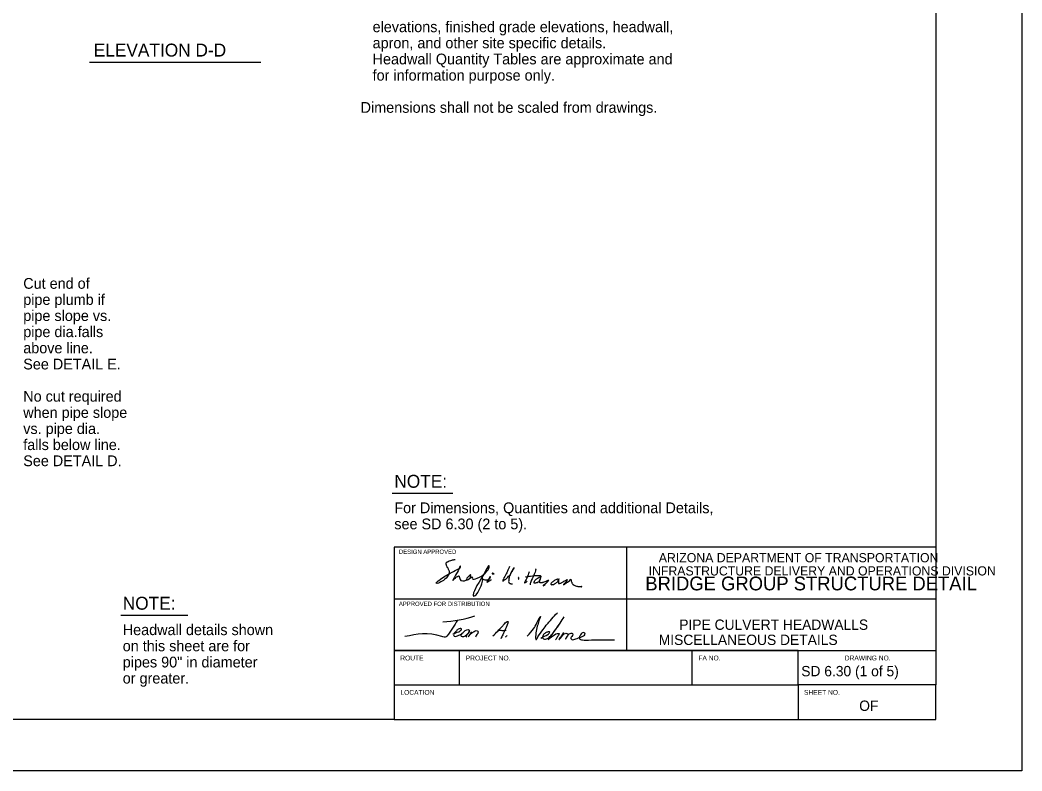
# Model space of a CAD drawing. Extents: x -0.08 to 2.83, y -0.03 to 1.92.
# Drawn here: x 1.621 to 2.833, y 0 to 0.909 of the extents above; entities that cross this region are included whole.
import ezdxf

# ---------------------------------------------------------------- set-up
doc = ezdxf.new("R2010")
doc.units = 0
for name, color, linetype in [('55', 7, 'Continuous'), ('57', 7, 'Continuous'), ('62', 7, 'Continuous'), ('63', 7, 'Continuous')]:
    doc.layers.add(name, color=color, linetype=linetype)

msp = doc.modelspace()

# ---------------------------------------------------------------- linework, layer by layer
at = {"layer": '57'}
for p, q in [((1.7051, 0.8577), (1.9125, 0.8577)), ((2.0713, 0.3361), (2.1448, 0.3361)), ((1.7428, 0.1885), (1.8239, 0.1885))]:
    msp.add_line(p, q, dxfattribs=at)
for points in [[(2.1477, 0.2556), (2.1468, 0.2557), (2.1458, 0.2554), (2.1449, 0.2553), (2.144, 0.255), (2.1431, 0.2548), (2.142, 0.2543), (2.1404, 0.2539), (2.139, 0.2533), (2.1381, 0.2528), (2.1376, 0.2526), (2.1371, 0.2524), (2.1366, 0.2519), (2.1364, 0.2514), (2.1363, 0.2504), (2.1365, 0.2499), (2.1367, 0.2491), (2.1371, 0.2482), (2.1375, 0.2473), (2.138, 0.2463), (2.1385, 0.2457), (2.1391, 0.2444), (2.1395, 0.2436), (2.1399, 0.2429), (2.1401, 0.2414), (2.1402, 0.2405), (2.1401, 0.2395), (2.1397, 0.238), (2.1389, 0.2363), (2.1382, 0.2352), (2.1366, 0.2333), (2.1351, 0.2323), (2.1333, 0.2307), (2.1317, 0.2297), (2.1303, 0.2288), (2.1288, 0.228), (2.1273, 0.2273), (2.1258, 0.2268), (2.125, 0.2269), (2.1246, 0.2276), (2.1248, 0.228), (2.1254, 0.2285), (2.1258, 0.2291), (2.1269, 0.23), (2.129, 0.2315), (2.1299, 0.2322), (2.1315, 0.2334), (2.1333, 0.2345), (2.1352, 0.2357), (2.1368, 0.2366), (2.1413, 0.2395), (2.1456, 0.2416), (2.1476, 0.2427), (2.1498, 0.2437), (2.1514, 0.2445), (2.1527, 0.2452), (2.1536, 0.2459), (2.154, 0.2465), (2.154, 0.2477), (2.1536, 0.2479), (2.1534, 0.2477), (2.1533, 0.2474), (2.1519, 0.2441), (2.151, 0.2423), (2.1479, 0.2371), (2.1462, 0.2339), (2.1454, 0.2326), (2.1446, 0.2309), (2.1447, 0.2307), (2.1462, 0.2324), (2.1479, 0.2338), (2.1493, 0.2349), (2.1504, 0.2355), (2.1503, 0.2355), (2.1517, 0.236), (2.1523, 0.2358), (2.1525, 0.2355), (2.1529, 0.2341), (2.153, 0.2328), (2.1535, 0.2316), (2.1542, 0.2306), (2.1566, 0.2301), (2.159, 0.2301), (2.1606, 0.2308), (2.1633, 0.2318), (2.1649, 0.233), (2.1659, 0.2341), (2.1662, 0.2362), (2.1665, 0.2374), (2.1662, 0.2377), (2.1657, 0.2374), (2.1644, 0.2361), (2.163, 0.2346), (2.1624, 0.234), (2.1617, 0.2332), (2.1613, 0.2319), (2.1615, 0.2311), (2.1631, 0.2319), (2.165, 0.2331), (2.1666, 0.2342), (2.1675, 0.2349)], [(2.1675, 0.2349), (2.1677, 0.235), (2.168, 0.235), (2.1683, 0.2343), (2.1681, 0.2332), (2.1685, 0.2325), (2.1694, 0.2323), (2.1707, 0.2323), (2.1722, 0.2326), (2.1743, 0.2334), (2.1771, 0.2347), (2.1792, 0.2359), (2.1811, 0.237), (2.184, 0.2394), (2.1867, 0.2425), (2.1874, 0.2434), (2.188, 0.2441), (2.1888, 0.2468), (2.1886, 0.2482), (2.188, 0.2484), (2.1852, 0.2437), (2.1836, 0.2401), (2.1786, 0.2322), (2.1764, 0.2285), (2.1737, 0.2244), (2.1708, 0.2182), (2.1698, 0.2158), (2.1692, 0.2126), (2.1693, 0.2119), (2.1701, 0.2114), (2.1719, 0.2123), (2.173, 0.2133), (2.1749, 0.2161), (2.1775, 0.2209), (2.1789, 0.2242), (2.1797, 0.2265), (2.1806, 0.2298), (2.1808, 0.2318), (2.1807, 0.2332), (2.1801, 0.2336), (2.1797, 0.2338), (2.18, 0.2331), (2.1807, 0.2327), (2.1813, 0.2322), (2.1824, 0.2317), (2.1835, 0.2313), (2.1841, 0.2313), (2.1858, 0.2312), (2.1865, 0.2313), (2.1879, 0.2317), (2.1891, 0.2327), (2.1894, 0.233), (2.1901, 0.2346), (2.1902, 0.2351), (2.1898, 0.2354), (2.1884, 0.2324), (2.1867, 0.2305), (2.1863, 0.2297), (2.186, 0.229), (2.1862, 0.2285), (2.1886, 0.23), (2.1895, 0.2305), (2.1906, 0.2312), (2.1914, 0.2318)], [(2.2132, 0.2473), (2.2128, 0.2463), (2.2119, 0.2446), (2.2111, 0.2429), (2.2099, 0.24), (2.2092, 0.2388), (2.2084, 0.2371), (2.2075, 0.2353), (2.2066, 0.2336), (2.2059, 0.2321), (2.2052, 0.2309), (2.205, 0.2303), (2.205, 0.23), (2.2051, 0.2299), (2.2054, 0.2298), (2.2057, 0.23), (2.2065, 0.2305), (2.2074, 0.2312), (2.2088, 0.2323), (2.2101, 0.2334), (2.2113, 0.2347), (2.2122, 0.2357), (2.2133, 0.2367), (2.214, 0.2375), (2.2148, 0.239), (2.216, 0.2409), (2.2167, 0.242), (2.2178, 0.2441), (2.2184, 0.2448), (2.2189, 0.2456), (2.2189, 0.2458), (2.2188, 0.2459), (2.2187, 0.246), (2.2185, 0.2459), (2.2181, 0.2452), (2.2172, 0.2441), (2.216, 0.242), (2.2157, 0.2413), (2.2153, 0.2404), (2.2149, 0.2396), (2.2139, 0.2375), (2.2133, 0.236), (2.213, 0.2348), (2.2127, 0.2337), (2.2125, 0.2324), (2.2123, 0.2307), (2.2122, 0.2295), (2.2123, 0.2283), (2.2126, 0.2278), (2.2132, 0.2273), (2.2138, 0.2269), (2.2143, 0.2267), (2.215, 0.2265), (2.2156, 0.2264), (2.2162, 0.2264), (2.2167, 0.2264)], [(2.2447, 0.2448), (2.245, 0.2443), (2.245, 0.2437), (2.2449, 0.2432), (2.2447, 0.2423), (2.2443, 0.2408), (2.2439, 0.2397), (2.2432, 0.238), (2.2427, 0.237), (2.2421, 0.2359), (2.241, 0.2334), (2.2406, 0.2326), (2.2395, 0.2304), (2.2393, 0.23), (2.239, 0.2291), (2.2386, 0.2277), (2.2384, 0.2267), (2.2382, 0.2256), (2.2381, 0.2252)], [(2.1947, 0.2388), (2.1943, 0.2388), (2.1938, 0.2389), (2.1934, 0.2391), (2.1931, 0.2393), (2.1928, 0.2393), (2.1925, 0.2393), (2.1924, 0.2392), (2.1922, 0.239), (2.1922, 0.2389), (2.1922, 0.2386), (2.1925, 0.2385), (2.1927, 0.2385), (2.193, 0.2385), (2.1935, 0.2386), (2.1938, 0.2386), (2.1942, 0.2386), (2.1946, 0.2387), (2.1947, 0.2387)], [(2.2244, 0.2324), (2.2247, 0.2331), (2.2246, 0.2338), (2.2244, 0.2341), (2.2241, 0.2341), (2.224, 0.2339), (2.2239, 0.2332), (2.224, 0.2326), (2.2242, 0.2323), (2.2243, 0.2322), (2.2244, 0.2322), (2.2244, 0.2324)], [(2.2371, 0.2412), (2.2367, 0.24), (2.2364, 0.239), (2.2358, 0.2372), (2.235, 0.2353), (2.2346, 0.2345), (2.2341, 0.2333), (2.2333, 0.2317), (2.2327, 0.2306), (2.2322, 0.2297), (2.2317, 0.2288), (2.2315, 0.2282), (2.2315, 0.2278), (2.2316, 0.2276), (2.2318, 0.2276), (2.232, 0.2276), (2.2326, 0.228), (2.2331, 0.2284), (2.2334, 0.2286), (2.2336, 0.2288), (2.2338, 0.2289), (2.234, 0.2291), (2.2342, 0.2293), (2.2344, 0.2295), (2.2345, 0.2296), (2.2347, 0.2298)], [(2.2325, 0.2346), (2.2332, 0.2348), (2.2342, 0.235), (2.2357, 0.2354), (2.2374, 0.2358), (2.2388, 0.2359), (2.2409, 0.2362), (2.243, 0.2364), (2.2448, 0.2366), (2.2463, 0.2366), (2.2475, 0.2366), (2.2482, 0.2366), (2.2495, 0.2365), (2.2505, 0.2364), (2.2509, 0.2362), (2.2511, 0.2357), (2.2507, 0.2337), (2.2506, 0.2334), (2.2501, 0.2318), (2.2497, 0.2308), (2.2492, 0.2298), (2.249, 0.2294), (2.2488, 0.2291), (2.2486, 0.2288), (2.2479, 0.2285), (2.2467, 0.2278), (2.2457, 0.2276), (2.2449, 0.2273), (2.2445, 0.2272), (2.244, 0.2272), (2.2435, 0.2274), (2.2433, 0.2275), (2.2433, 0.2277), (2.2433, 0.2281), (2.2433, 0.2288), (2.2435, 0.2293), (2.2437, 0.2298), (2.2441, 0.2306), (2.2447, 0.2312), (2.2456, 0.2321), (2.2463, 0.2326), (2.2468, 0.233), (2.2474, 0.2335), (2.2481, 0.2339), (2.249, 0.2344), (2.2496, 0.2347), (2.2503, 0.235), (2.2505, 0.235), (2.2508, 0.2349), (2.2508, 0.2347), (2.2506, 0.2334), (2.2505, 0.2332), (2.2503, 0.2322), (2.2499, 0.231), (2.2495, 0.23), (2.2494, 0.2295), (2.2494, 0.2293), (2.2493, 0.2291), (2.2493, 0.2287), (2.2494, 0.2284), (2.2498, 0.2281), (2.2499, 0.228), (2.2501, 0.228), (2.2505, 0.228), (2.2511, 0.228), (2.2515, 0.228), (2.2519, 0.2281), (2.2525, 0.2282), (2.2531, 0.2283), (2.2537, 0.2284), (2.2544, 0.2285), (2.2551, 0.2288), (2.2563, 0.2293), (2.2578, 0.2299), (2.2589, 0.2304), (2.2597, 0.2307), (2.2602, 0.231), (2.2608, 0.2311), (2.2609, 0.231), (2.2606, 0.2304), (2.26, 0.2298), (2.2593, 0.229), (2.2589, 0.2286), (2.2583, 0.228), (2.2572, 0.227), (2.2541, 0.2242), (2.2538, 0.224), (2.2541, 0.2241), (2.255, 0.2245), (2.2558, 0.2249), (2.2563, 0.2251), (2.2566, 0.2253)], [(2.2723, 0.2303), (2.2721, 0.2318), (2.2715, 0.2323), (2.271, 0.2321), (2.2692, 0.2314), (2.2681, 0.2308), (2.2672, 0.2302), (2.2664, 0.2297), (2.2655, 0.229), (2.2647, 0.2284), (2.2642, 0.2278), (2.2637, 0.2272), (2.2634, 0.2266), (2.2634, 0.2263), (2.2634, 0.2259), (2.2637, 0.2256), (2.264, 0.2255), (2.2644, 0.2254), (2.2646, 0.2254), (2.2652, 0.2255), (2.2655, 0.2256), (2.2664, 0.2258), (2.2678, 0.2263), (2.2686, 0.2269), (2.2695, 0.2275), (2.2703, 0.2281), (2.2711, 0.2287), (2.2718, 0.2294), (2.2724, 0.2301), (2.2731, 0.2315), (2.2732, 0.2322), (2.273, 0.2327), (2.2727, 0.2323), (2.2726, 0.2317), (2.2726, 0.231), (2.2726, 0.2299), (2.2726, 0.2291), (2.2726, 0.2283), (2.2726, 0.2277), (2.2726, 0.2269), (2.2727, 0.2267), (2.2728, 0.2267), (2.2737, 0.227), (2.2747, 0.2272), (2.2754, 0.2275), (2.2761, 0.2279), (2.2764, 0.228), (2.2772, 0.2284), (2.278, 0.2288), (2.2792, 0.2296), (2.2804, 0.2302), (2.2817, 0.2309), (2.2821, 0.2312), (2.283, 0.2318), (2.2831, 0.2317), (2.2829, 0.231), (2.2826, 0.2303), (2.2822, 0.2296), (2.2816, 0.2287), (2.2811, 0.2281), (2.2799, 0.2268), (2.2786, 0.2256), (2.2785, 0.2253), (2.2787, 0.2253), (2.2801, 0.2263), (2.2819, 0.2276), (2.2834, 0.2286), (2.2845, 0.2294), (2.2857, 0.2303), (2.287, 0.2318), (2.2871, 0.2318), (2.2873, 0.2321), (2.2874, 0.232), (2.2877, 0.2307), (2.2879, 0.2299), (2.2882, 0.229), (2.2885, 0.2284), (2.2888, 0.2277), (2.2891, 0.2271), (2.2896, 0.2263), (2.29, 0.2258), (2.2905, 0.2255), (2.2909, 0.2251), (2.2913, 0.2249), (2.2923, 0.2244), (2.2932, 0.2241), (2.2944, 0.2237), (2.2951, 0.2236), (2.2961, 0.2234), (2.297, 0.2233), (2.298, 0.2232), (2.2988, 0.2232), (2.2995, 0.2231), (2.3005, 0.223), (2.3009, 0.2229), (2.3007, 0.2231), (2.3004, 0.2233), (2.3001, 0.2235), (2.2999, 0.2236)]]:
    msp.add_lwpolyline(points, dxfattribs=at)
msp.add_arc((2.1258, 0.3265), 0.1461, 272.671, 288.185, dxfattribs=at)
msp.add_ellipse((2.1597, 0.1667), major_axis=(0.00445, 0.00414), ratio=0.425517, dxfattribs=at)
for points in [[(2.1503, 0.1825), (2.1375, 0.1632), (2.1366, 0.1623), (2.1312, 0.1628), (2.0868, 0.1626)], [(2.2347, 0.1633), (2.2425, 0.1721), (2.2468, 0.1799), (2.2506, 0.1869), (2.2498, 0.1845), (2.2487, 0.1817), (2.2479, 0.1785), (2.2459, 0.1712), (2.2458, 0.1593), (2.2477, 0.1622), (2.2538, 0.1711), (2.2591, 0.178), (2.2628, 0.1822), (2.2695, 0.1897), (2.2712, 0.1915)], [(2.2791, 0.1865), (2.2669, 0.1687), (2.26, 0.1588), (2.271, 0.1664), (2.2717, 0.1665), (2.2732, 0.1663), (2.2731, 0.1653), (2.2715, 0.1627), (2.269, 0.1586)], [(2.1447, 0.166), (2.1519, 0.1686), (2.154, 0.1699), (2.155, 0.1715), (2.155, 0.1722), (2.1537, 0.1723), (2.1511, 0.1715), (2.1483, 0.1689), (2.1465, 0.1668), (2.1457, 0.1646), (2.1463, 0.1633), (2.1491, 0.1632), (2.153, 0.1646), (2.1551, 0.1658), (2.1571, 0.1674), (2.1572, 0.1674)], [(2.1642, 0.1709), (2.1647, 0.1696), (2.1632, 0.1667), (2.1612, 0.1643), (2.1608, 0.1628), (2.1615, 0.1621)], [(2.1673, 0.1685), (2.1658, 0.1661), (2.1634, 0.1622), (2.1659, 0.1656), (2.1691, 0.168), (2.1705, 0.169), (2.1749, 0.1692), (2.1752, 0.1678), (2.1748, 0.1663), (2.1729, 0.1639), (2.172, 0.1618)], [(2.1932, 0.1635), (2.199, 0.1693), (2.205, 0.1757), (2.2072, 0.1782), (2.2094, 0.1803), (2.2114, 0.181), (2.2113, 0.1794), (2.2108, 0.1779), (2.2091, 0.1736), (2.205, 0.1646), (2.2028, 0.16)], [(2.2002, 0.1702), (2.2027, 0.1703), (2.2053, 0.1701), (2.2092, 0.1703)], [(2.251, 0.1608), (2.2596, 0.1653), (2.261, 0.1663), (2.262, 0.1678), (2.2617, 0.1682), (2.26, 0.1684), (2.2567, 0.1671), (2.254, 0.1642), (2.2533, 0.162), (2.2533, 0.161), (2.2558, 0.1596), (2.2601, 0.1609), (2.2641, 0.1646), (2.2731, 0.1773)], [(2.2099, 0.1638), (2.2091, 0.1627), (2.2081, 0.162)], [(2.2788, 0.1674), (2.2734, 0.1591), (2.2738, 0.1595), (2.2796, 0.1659), (2.2814, 0.1666), (2.2834, 0.166), (2.2837, 0.1642), (2.2827, 0.1623), (2.2811, 0.1599), (2.2835, 0.1633), (2.2855, 0.166), (2.2896, 0.1665), (2.2894, 0.164), (2.2876, 0.1603), (2.288, 0.1599), (2.2888, 0.1592), (2.2935, 0.1599), (2.2997, 0.162), (2.3027, 0.1636), (2.3049, 0.1657), (2.3035, 0.1673), (2.3, 0.1659), (2.2983, 0.1632), (2.2979, 0.1623), (2.2978, 0.1605), (2.3016, 0.1586), (2.3087, 0.1584), (2.3405, 0.1588)]]:
    msp.add_spline(points, degree=3, dxfattribs=at)
at = {"layer": '63'}
for p, q in [((2.8333, 1.8333), (2.8333, 0)), ((2.7292, 0.2708), (2.0739, 0.2708)), ((2.0739, 0.2708), (2.0739, 0.0624)), ((2.3549, 0.2708), (2.3549, 0.1458)), ((2.0739, 0.2083), (2.7292, 0.2083)), ((2.0739, 0.2065), (2.0739, 0.2065)), ((2.0739, 0.2065), (2.0739, 0.2065)), ((2.0739, 0.1458), (2.7292, 0.1458)), ((2.0891, 0.1458), (2.0893, 0.1458)), ((2.1527, 0.1041), (2.1527, 0.1458)), ((2.4343, 0.1041), (2.4343, 0.1458)), ((2.0739, 0.144), (2.0739, 0.144)), ((2.0739, 0.1041), (2.5625, 0.1041)), ((2.5625, 0.1041), (2.5625, 0.0624)), ((2.7292, 0.0624), (2.7292, 0.1041)), ((2.0739, 0.0624), (2.7292, 0.0624)), ((2.8333, 0), (0, 0)), ((2.83, 0.0003), (2.83, 0.0003))]:
    msp.add_line(p, q, dxfattribs=at)
msp.add_lwpolyline([(0.1667, 0.0624), (0.1667, 1.7708), (2.7292, 1.7708), (2.7292, 0.1041), (2.5625, 0.1041), (2.5625, 0.1458), (2.0739, 0.1458), (2.0739, 0.0624)], close=True, dxfattribs=at)

# ---------------------------------------------------------------- texts
at = {"layer": '55'}
for s, p in [('DESIGN APPROVED', (2.0794, 0.2627)), ('APPROVED FOR DISTRIBUTION', (2.0794, 0.1997))]:
    msp.add_text(s, height=0.005208, dxfattribs=at).set_placement(p)
at = {"layer": '57'}
for s, height, p in [('   elevations, finished grade elevations, headwall,', 0.013021, (2.0331, 0.8942)), ('   apron, and other site specific details.', 0.013021, (2.0331, 0.8747)), ('ELEVATION D-D', 0.015625, (1.7102, 0.8647)), ('   Headwall Quantity Tables are approximate and', 0.013021, (2.0331, 0.8552)), ('   for information purpose only.', 0.013021, (2.0331, 0.8356)), ('Dimensions shall not be scaled from drawings.', 0.013021, (2.0331, 0.7966)), ('Cut end of', 0.01302, (1.6249, 0.5836)), ('pipe plumb if', 0.013017, (1.6249, 0.5641)), ('pipe slope vs.', 0.013017, (1.6249, 0.5446)), ('pipe dia.falls', 0.013017, (1.6249, 0.5251)), ('above line.', 0.013017, (1.6249, 0.5055)), ('See DETAIL E.', 0.013017, (1.6249, 0.486)), ('No cut required', 0.013017, (1.6249, 0.447)), ('when pipe slope', 0.013017, (1.6249, 0.4274)), ('vs. pipe dia.', 0.013017, (1.6249, 0.4079)), ('falls below line.', 0.013017, (1.6249, 0.3884)), ('See DETAIL D.', 0.013017, (1.6249, 0.3689)), ('NOTE:', 0.01562, (2.0739, 0.3428)), ('For Dimensions, Quantities and additional Details,', 0.013021, (2.0739, 0.312)), ('see SD 6.30 (2 to 5).', 0.013021, (2.0739, 0.2925)), ('NOTE:', 0.01562, (1.7453, 0.1952)), ('Headwall details shown', 0.013021, (1.7453, 0.1644)), ('on this sheet are for', 0.013021, (1.7453, 0.1449)), ('pipes 90" in diameter', 0.013021, (1.7453, 0.1253)), ('or greater.', 0.013021, (1.7453, 0.1058))]:
    msp.add_text(s, height=height, dxfattribs=at).set_placement(p)
at = {"layer": '62'}
for s, p in [('PIPE CULVERT HEADWALLS', (2.4187, 0.1708)), ('      MISCELLANEOUS DETAILS     ', (2.366, 0.1525)), ('SD 6.30 (1 of 5)', (2.5663, 0.1146))]:
    msp.add_text(s, height=0.0125, dxfattribs=at).set_placement(p)
at = {"layer": '63'}
for s, height, p in [('ARIZONA DEPARTMENT OF TRANSPORTATION', 0.011108, (2.3939, 0.2526)), ('INFRASTRUCTURE DELIVERY AND OPERATIONS DIVISION', 0.011108, (2.3816, 0.2366)), ('BRIDGE GROUP STRUCTURE DETAIL', 0.016667, (2.3776, 0.2186)), ('ROUTE', 0.00583, (2.0811, 0.1338)), ('PROJECT NO.', 0.005833, (2.1603, 0.1338)), ('FA NO.', 0.00583, (2.4418, 0.1338)), ('DRAWING NO.', 0.005833, (2.6189, 0.1338)), ('LOCATION', 0.00583, (2.0813, 0.0922)), ('SHEET NO.', 0.00583, (2.5696, 0.0922)), ('OF', 0.0125, (2.6364, 0.0727))]:
    msp.add_text(s, height=height, dxfattribs=at).set_placement(p)

doc.saveas('drawing.dxf')
